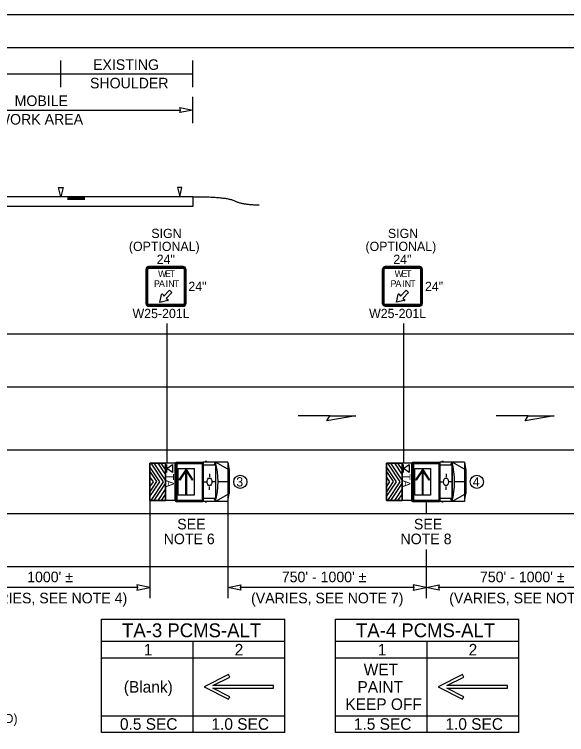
# Model space of a CAD drawing. Extents: x 0 to 17, y 0 to 11.
# Drawn here: x 8.5 to 12.68, y 5.55 to 11 of the extents above; entities that cross this region are included whole.
import ezdxf

# ---------------------------------------------------------------- set-up
doc = ezdxf.new("R2010")
doc.units = 0
for name, color, linetype in [('RD_ED_ShoulderPavedEdge', 7, 'Continuous'), ('RD_MK_LineEdgeWhite', 7, 'Continuous'), ('RD_MK_LineEdgeYellow', 7, 'Continuous'), ('RD_MK_LineLane', 7, 'Continuous'), ('SH_GI_PlotLimits', 7, 'Continuous'), ('SH_GI_SheetBorder3', 7, 'Continuous'), ('SH_TI_WZSectionCut', 7, 'Continuous'), ('TR_SN_ConstructionSigns', 7, 'Continuous'), ('TR_SN_SignNotes', 7, 'Continuous'), ('TR_WZ_PortableChangeMessageSign', 7, 'Continuous'), ('TR_WZ_PortableSignMountBlk-Org', 7, 'Continuous'), ('TR_WZ_TransportableAttenuator', 7, 'Continuous'), ('TR_WZ_WorkZoneDetails', 7, 'Continuous'), ('TR_WZ_WorkZoneTextCurrent', 7, 'Continuous')]:
    doc.layers.add(name, color=color, linetype=linetype)

msp = doc.modelspace()

# ---------------------------------------------------------------- linework, layer by layer
at = {"layer": 'RD_ED_ShoulderPavedEdge'}
for p, q in [((1.8283, 8.5807), (16.62, 8.5807)), ((1.8283, 6.8207), (16.62, 6.8207))]:
    msp.add_line(p, q, dxfattribs=at)
at = {"layer": 'RD_MK_LineEdgeWhite'}
msp.add_line((1.8283, 7.2207), (16.62, 7.2207), dxfattribs=at)
at = {"layer": 'RD_MK_LineEdgeYellow'}
msp.add_line((1.8283, 8.1807), (16.62, 8.1807), dxfattribs=at)
at = {"layer": 'RD_MK_LineLane'}
msp.add_line((16.62, 7.7007), (1.8283, 7.7007), dxfattribs=at)
at = {"layer": 'SH_GI_PlotLimits'}
msp.add_lwpolyline([(0, 11), (17, 11), (17, 0), (0, 0)], close=True, dxfattribs=at)
at = {"layer": 'SH_GI_SheetBorder3'}
msp.add_line((1, 10.75), (16.75, 10.75), dxfattribs=at)
at = {"layer": 'SH_TI_WZSectionCut'}
for p, q in [((8.8546, 10.45), (8.8546, 10.65)), ((9.8546, 10.45), (9.8546, 10.65)), ((7.6546, 10.55), (8.8546, 10.55)), ((8.8546, 10.55), (9.8546, 10.55)), ((9.8546, 10.176), (9.8546, 10.376)), ((7.6484, 10.276), (9.7609, 10.276)), ((9.8546, 9.6199), (5.4546, 9.6199)), ((9.0376, 9.6143), (8.9046, 9.6143)), ((9.0376, 9.6087), (8.9046, 9.6087)), ((9.0376, 9.603), (8.9046, 9.603)), ((9.0376, 9.5978), (8.9046, 9.5978)), ((9.8546, 9.6199), (9.8546, 9.5449)), ((9.8546, 9.5449), (5.4546, 9.5449))]:
    msp.add_line(p, q, dxfattribs=at)
for points in [[(9.8546, 10.276), (9.7564, 10.2567), (9.7609, 10.276), (9.7564, 10.2953)], [(8.838, 9.6897), (8.8713, 9.6897), (8.8547, 9.6199)]]:
    msp.add_lwpolyline(points, close=True, dxfattribs=at)
msp.add_lwpolyline([(9.7713, 9.6897), (9.7379, 9.6897), (9.7546, 9.6199), (9.7713, 9.6897)], dxfattribs=at)
msp.add_open_spline([(9.8546, 9.6199), (10.1058, 9.6201), (10.2313, 9.558), (10.3568, 9.5581)], degree=2, dxfattribs=at)
at = {"layer": 'TR_SN_ConstructionSigns'}
for p, q in [((9.5003, 9.0719), (9.5003, 8.8094)), ((9.5003, 8.8094), (9.5003, 9.0719)), ((9.5003, 9.0719), (9.5003, 8.8094)), ((9.505, 9.0719), (9.505, 8.8094)), ((9.5128, 8.8094), (9.5128, 9.0719)), ((9.7816, 9.0907), (9.5191, 9.0907)), ((9.5191, 9.0907), (9.7816, 9.0907)), ((9.7816, 9.0907), (9.5191, 9.0907)), ((9.7816, 9.086), (9.5191, 9.086)), ((9.5191, 9.0782), (9.7816, 9.0782)), ((9.7878, 9.0719), (9.7878, 8.8094)), ((9.7956, 8.8094), (9.7956, 9.0719)), ((9.8003, 8.8094), (9.8003, 9.0719)), ((9.8003, 9.0719), (9.8003, 8.8094)), ((9.8003, 8.8094), (9.8003, 9.0719)), ((11.2911, 9.072), (11.2911, 8.8095)), ((11.2911, 8.8095), (11.2911, 9.072)), ((11.2911, 9.072), (11.2911, 8.8095)), ((11.2958, 9.072), (11.2958, 8.8095)), ((11.3036, 8.8095), (11.3036, 9.072)), ((11.5723, 9.0907), (11.3098, 9.0907)), ((11.3098, 9.0907), (11.5723, 9.0907)), ((11.5723, 9.0907), (11.3098, 9.0907)), ((11.5723, 9.086), (11.3098, 9.086)), ((11.3098, 9.0782), (11.5723, 9.0782)), ((11.5786, 9.072), (11.5786, 8.8095)), ((11.5864, 8.8095), (11.5864, 9.072)), ((11.5911, 8.8095), (11.5911, 9.072)), ((11.5911, 9.072), (11.5911, 8.8095)), ((11.5911, 8.8095), (11.5911, 9.072)), ((9.6343, 8.8674), (9.6785, 8.9115)), ((9.6962, 8.8939), (9.652, 8.8497)), ((9.6785, 8.9115), (9.6962, 8.8939)), ((11.4251, 8.8674), (11.4693, 8.9116)), ((11.4869, 8.8939), (11.4427, 8.8497)), ((11.4693, 8.9116), (11.4869, 8.8939)), ((9.6045, 8.8198), (9.6176, 8.8796)), ((9.6261, 8.8808), (9.6343, 8.8674)), ((9.652, 8.8497), (9.6654, 8.8415)), ((11.3952, 8.8199), (11.4084, 8.8796)), ((11.4169, 8.8809), (11.4251, 8.8674)), ((11.4427, 8.8497), (11.4562, 8.8416)), ((9.7816, 8.8032), (9.5191, 8.8032)), ((9.5191, 8.7954), (9.7816, 8.7954)), ((9.5191, 8.7907), (9.7816, 8.7907)), ((9.7816, 8.7907), (9.5191, 8.7907)), ((9.5191, 8.7907), (9.7816, 8.7907)), ((9.6642, 8.833), (9.6045, 8.8198)), ((11.5723, 8.8032), (11.3098, 8.8032)), ((11.3098, 8.7954), (11.5723, 8.7954)), ((11.3098, 8.7907), (11.5723, 8.7907)), ((11.5723, 8.7907), (11.3098, 8.7907)), ((11.3098, 8.7907), (11.5723, 8.7907)), ((11.455, 8.833), (11.3952, 8.8199))]:
    msp.add_line(p, q, dxfattribs=at)
for centre, radius, start, end in [((9.5191, 9.0719), 0.0188, 90, 180), ((9.5191, 9.0719), 0.0188, 90, 180), ((9.5191, 9.0719), 0.0188, 90, 180), ((9.5191, 9.0719), 0.0141, 90, 180), ((9.5191, 9.0719), 0.00625, 90, 180), ((9.7816, 9.0719), 0.0188, 0, 90), ((9.7816, 9.0719), 0.0188, 0, 90), ((9.7816, 9.0719), 0.0188, 0, 90), ((9.7816, 9.0719), 0.0141, 0, 90), ((9.7816, 9.0719), 0.00625, 0, 90), ((11.3098, 9.072), 0.0188, 90, 180), ((11.3098, 9.072), 0.0188, 90, 180), ((11.3098, 9.072), 0.0188, 90, 180), ((11.3098, 9.072), 0.0141, 90, 180), ((11.3098, 9.072), 0.00625, 90, 180), ((11.5723, 9.072), 0.0188, 0, 90), ((11.5723, 9.072), 0.0188, 0, 90), ((11.5723, 9.072), 0.0188, 0, 90), ((11.5723, 9.072), 0.0141, 0, 90), ((11.5723, 9.072), 0.00625, 0, 90), ((9.6221, 8.8784), 0.00469, 31.1441, 165.4258), ((9.663, 8.8375), 0.00469, 284.5742, 58.8559), ((11.4129, 8.8784), 0.00469, 31.1441, 165.4258), ((11.4538, 8.8376), 0.00469, 284.5742, 58.8559), ((9.5191, 8.8094), 0.0188, 180, 270), ((9.5191, 8.8094), 0.0188, 180, 270), ((9.5191, 8.8094), 0.0188, 180, 270), ((9.5191, 8.8094), 0.0141, 180, 270), ((9.5191, 8.8094), 0.00625, 180, 270), ((9.7816, 8.8094), 0.0141, 270, 0), ((9.7816, 8.8094), 0.00625, 270, 0), ((9.7816, 8.8094), 0.0188, 270, 0), ((9.7816, 8.8094), 0.0188, 270, 0), ((9.7816, 8.8094), 0.0188, 270, 0), ((11.3098, 8.8095), 0.0188, 180, 270), ((11.3098, 8.8095), 0.0188, 180, 270), ((11.3098, 8.8095), 0.0188, 180, 270), ((11.3098, 8.8095), 0.0141, 180, 270), ((11.3098, 8.8095), 0.00625, 180, 270), ((11.5723, 8.8095), 0.0141, 270, 0), ((11.5723, 8.8095), 0.00625, 270, 0), ((11.5723, 8.8095), 0.0188, 270, 0), ((11.5723, 8.8095), 0.0188, 270, 0), ((11.5723, 8.8095), 0.0188, 270, 0)]:
    msp.add_arc(centre, radius, start, end, dxfattribs=at)
at = {"layer": 'TR_SN_SignNotes'}
for centre in [(9.98, 7.4607), (11.7708, 7.4607)]:
    msp.add_ellipse(centre, major_axis=(0, 0.0289), ratio=0.642144, dxfattribs=at)
at = {"layer": 'TR_WZ_PortableChangeMessageSign'}
for p, q in [((9.1639, 6.4207), (10.5499, 6.4207)), ((9.1639, 5.5639), (9.1639, 6.4207)), ((10.5499, 5.5639), (10.5499, 6.4207)), ((10.9348, 6.4207), (12.3208, 6.4207)), ((10.9348, 5.5639), (10.9348, 6.4207)), ((12.3208, 5.5639), (12.3208, 6.4207)), ((10.5499, 6.2527), (9.1639, 6.2527)), ((9.8569, 5.5639), (9.8569, 6.2527)), ((12.3208, 6.2527), (10.9348, 6.2527)), ((11.6278, 5.5639), (11.6278, 6.2527)), ((9.8569, 6.1267), (9.1639, 6.1267)), ((10.5499, 6.1267), (9.8569, 6.1267)), ((11.6278, 6.1267), (10.9348, 6.1267)), ((12.3208, 6.1267), (11.6278, 6.1267)), ((10.1249, 6.0017), (9.9409, 5.9083)), ((11.8958, 6.0017), (11.7118, 5.9083)), ((10.4659, 5.9188), (10.006, 5.9188)), ((10.006, 5.8978), (10.4659, 5.8978)), ((10.4659, 5.8978), (10.4659, 5.9188)), ((12.2368, 5.9188), (11.777, 5.9188)), ((11.777, 5.8978), (12.2368, 5.8978)), ((12.2368, 5.8978), (12.2368, 5.9188)), ((9.1639, 5.6899), (9.8569, 5.6899)), ((9.8569, 5.6899), (10.5499, 5.6899)), ((10.9348, 5.6899), (11.6278, 5.6899)), ((11.6278, 5.6899), (12.3208, 5.6899)), ((10.5499, 5.5639), (9.1639, 5.5639)), ((12.3208, 5.5639), (10.9348, 5.5639))]:
    msp.add_line(p, q, dxfattribs=at)
for points in [[(10.006, 5.9188), (10.1342, 5.9829), (10.1296, 5.9923), (10.1249, 6.0017)], [(11.777, 5.9188), (11.9052, 5.9829), (11.9005, 5.9923), (11.8958, 6.0017)], [(9.9409, 5.9083), (10.1249, 5.8149), (10.1296, 5.8243), (10.1342, 5.8337), (10.006, 5.8978)], [(11.7118, 5.9083), (11.8958, 5.8149), (11.9005, 5.8243), (11.9052, 5.8337), (11.777, 5.8978)]]:
    msp.add_lwpolyline(points, dxfattribs=at)
at = {"layer": 'TR_WZ_PortableSignMountBlk-Org'}
for p, q in [((9.6581, 7.5319), (9.6581, 7.5919)), ((11.4489, 7.5319), (11.4489, 7.5919))]:
    msp.add_line(p, q, dxfattribs=at)
for points in [[(9.6581, 7.5619), (9.7012, 7.5919), (9.7012, 7.5319)], [(11.4489, 7.5619), (11.492, 7.5919), (11.492, 7.5319)]]:
    msp.add_lwpolyline(points, close=True, dxfattribs=at)
at = {"layer": 'TR_WZ_TransportableAttenuator'}
for p, q in [((9.5368, 7.6018), (9.5623, 7.6018)), ((9.5368, 7.6018), (9.6303, 7.4609)), ((9.5623, 7.6018), (9.5368, 7.6018)), ((9.6469, 7.4734), (9.5623, 7.6018)), ((9.5899, 7.6018), (9.6153, 7.6018)), ((9.6153, 7.6018), (9.5899, 7.6018)), ((9.5899, 7.6018), (9.6469, 7.5149)), ((9.6469, 7.5541), (9.6153, 7.6018)), ((9.7274, 7.6018), (9.6469, 7.6018)), ((9.6469, 7.3202), (9.6469, 7.6018)), ((9.7179, 7.5966), (9.7179, 7.3248)), ((9.7223, 7.6057), (9.7267, 7.6057)), ((9.7267, 7.6057), (9.7267, 7.3156)), ((9.7274, 7.6106), (9.9305, 7.6106)), ((9.7274, 7.6106), (9.7274, 7.3107)), ((9.7274, 7.6013), (9.7274, 7.3202)), ((9.7332, 7.5987), (9.7332, 7.3227)), ((9.7332, 7.5987), (9.9248, 7.5987)), ((9.9248, 7.5987), (9.9248, 7.3227)), ((9.9305, 7.6106), (9.9305, 7.3107)), ((9.9333, 7.6106), (9.9333, 7.3107)), ((10.1197, 7.6106), (9.9333, 7.6106)), ((10.0248, 7.5874), (9.9333, 7.5874)), ((9.9599, 7.615), (9.9487, 7.615)), ((10.0248, 7.6106), (10.0129, 7.5874)), ((10.0248, 7.6106), (10.0248, 7.3107)), ((10.0265, 7.6106), (10.0265, 7.3107)), ((10.1197, 7.5557), (10.0265, 7.6106)), ((10.1197, 7.6106), (10.1197, 7.3107)), ((10.1197, 7.6106), (10.1289, 7.5501)), ((11.3276, 7.6018), (11.3531, 7.6018)), ((11.3276, 7.6018), (11.4211, 7.4609)), ((11.3531, 7.6018), (11.3276, 7.6018)), ((11.4377, 7.4734), (11.3531, 7.6018)), ((11.3807, 7.6018), (11.4061, 7.6018)), ((11.4061, 7.6018), (11.3807, 7.6018)), ((11.3807, 7.6018), (11.4377, 7.5149)), ((11.4377, 7.5541), (11.4061, 7.6018)), ((11.5182, 7.6018), (11.4377, 7.6018)), ((11.4377, 7.3202), (11.4377, 7.6018)), ((11.5087, 7.5966), (11.5087, 7.3248)), ((11.5131, 7.6057), (11.5175, 7.6057)), ((11.5175, 7.6057), (11.5175, 7.3156)), ((11.5182, 7.6106), (11.7213, 7.6106)), ((11.5182, 7.6106), (11.5182, 7.3107)), ((11.5182, 7.6013), (11.5182, 7.3202)), ((11.524, 7.5987), (11.524, 7.3227)), ((11.524, 7.5987), (11.7155, 7.5987)), ((11.7155, 7.5987), (11.7155, 7.3227)), ((11.7213, 7.6106), (11.7213, 7.3107)), ((11.724, 7.6106), (11.724, 7.3107)), ((11.9105, 7.6106), (11.724, 7.6106)), ((11.8156, 7.5874), (11.724, 7.5874)), ((11.7507, 7.615), (11.7395, 7.615)), ((11.8156, 7.6106), (11.8037, 7.5874)), ((11.8156, 7.6106), (11.8156, 7.3107)), ((11.8172, 7.6106), (11.8172, 7.3107)), ((11.9105, 7.5557), (11.8172, 7.6106)), ((11.9105, 7.6106), (11.9105, 7.3107)), ((11.9105, 7.6106), (11.9197, 7.5501)), ((9.529, 7.5385), (9.529, 7.575)), ((9.6042, 7.4618), (9.529, 7.575)), ((9.529, 7.575), (9.529, 7.5385)), ((9.529, 7.5385), (9.58, 7.4622)), ((9.6469, 7.5541), (9.6469, 7.5149)), ((9.6469, 7.5149), (9.6469, 7.5541)), ((10.1289, 7.5501), (10.1289, 7.3713)), ((11.3198, 7.5385), (11.3198, 7.575)), ((11.3949, 7.4618), (11.3198, 7.575)), ((11.3198, 7.575), (11.3198, 7.5385)), ((11.3198, 7.5385), (11.3708, 7.4622)), ((11.4377, 7.5541), (11.4377, 7.5149)), ((11.4377, 7.5149), (11.4377, 7.5541)), ((11.9197, 7.5501), (11.9197, 7.3713)), ((9.529, 7.4219), (9.529, 7.4999)), ((9.5551, 7.4611), (9.529, 7.4999)), ((9.529, 7.4999), (9.529, 7.4219)), ((9.6469, 7.4734), (9.6469, 7.4483)), ((9.6469, 7.4483), (9.6469, 7.4734)), ((9.7179, 7.4818), (9.7267, 7.4762)), ((9.9801, 7.5201), (9.98, 7.4959)), ((11.3198, 7.4219), (11.3198, 7.4999)), ((11.3459, 7.4611), (11.3198, 7.4999)), ((11.3198, 7.4999), (11.3198, 7.4219)), ((11.4377, 7.4734), (11.4377, 7.4483)), ((11.4377, 7.4483), (11.4377, 7.4734)), ((11.5087, 7.4818), (11.5175, 7.4762)), ((11.7708, 7.5201), (11.7708, 7.4959)), ((9.58, 7.4622), (9.529, 7.3854)), ((9.529, 7.3486), (9.6042, 7.4618)), ((9.529, 7.4219), (9.5551, 7.4611)), ((9.6303, 7.4609), (9.5367, 7.32)), ((9.5618, 7.32), (9.6469, 7.4483)), ((9.7179, 7.4395), (9.7267, 7.4452)), ((9.7203, 7.4607), (9.7243, 7.4607)), ((9.7223, 7.4649), (9.7223, 7.4564)), ((9.9403, 7.4609), (9.9569, 7.4608)), ((9.9615, 7.4601), (9.9615, 7.4601)), ((9.9801, 7.4012), (9.98, 7.4255)), ((10.0197, 7.4609), (10.0031, 7.4608)), ((10.1197, 7.4607), (10.0448, 7.4607)), ((11.3708, 7.4622), (11.3198, 7.3854)), ((11.3198, 7.3486), (11.3949, 7.4618)), ((11.3198, 7.4219), (11.3459, 7.4611)), ((11.4211, 7.4609), (11.3275, 7.32)), ((11.3526, 7.32), (11.4377, 7.4483)), ((11.5087, 7.4395), (11.5175, 7.4452)), ((11.511, 7.4607), (11.5151, 7.4607)), ((11.5131, 7.4649), (11.5131, 7.4564)), ((11.7311, 7.4609), (11.7477, 7.4608)), ((11.7523, 7.4601), (11.7523, 7.4601)), ((11.7708, 7.4012), (11.7708, 7.4255)), ((11.8105, 7.4609), (11.7939, 7.4608)), ((11.9105, 7.4607), (11.8356, 7.4607)), ((9.529, 7.3486), (9.529, 7.3854)), ((9.529, 7.3854), (9.529, 7.3486)), ((9.6469, 7.4068), (9.5893, 7.32)), ((9.6162, 7.32), (9.6469, 7.3654)), ((9.6469, 7.4068), (9.6469, 7.3654)), ((9.6469, 7.3654), (9.6469, 7.4068)), ((10.1197, 7.3656), (10.0265, 7.3107)), ((10.1197, 7.3107), (10.1289, 7.3713)), ((11.3198, 7.3486), (11.3198, 7.3854)), ((11.3198, 7.3854), (11.3198, 7.3486)), ((11.4377, 7.4068), (11.3801, 7.32)), ((11.407, 7.32), (11.4377, 7.3654)), ((11.4377, 7.4068), (11.4377, 7.3654)), ((11.4377, 7.3654), (11.4377, 7.4068)), ((11.9105, 7.3656), (11.8172, 7.3107)), ((11.9105, 7.3107), (11.9197, 7.3713)), ((9.5618, 7.32), (9.5367, 7.32)), ((9.5367, 7.32), (9.5618, 7.32)), ((9.6162, 7.32), (9.5893, 7.32)), ((9.5893, 7.32), (9.6162, 7.32)), ((9.7274, 7.3202), (9.6469, 7.3202)), ((9.7223, 7.3156), (9.7267, 7.3156)), ((9.7274, 7.3107), (9.9305, 7.3107)), ((9.7332, 7.3227), (9.9248, 7.3227)), ((10.0248, 7.3339), (9.9333, 7.3339)), ((10.1197, 7.3107), (9.9333, 7.3107)), ((10.015, 7.3339), (10.0248, 7.3107)), ((11.3526, 7.32), (11.3275, 7.32)), ((11.3275, 7.32), (11.3526, 7.32)), ((11.407, 7.32), (11.3801, 7.32)), ((11.3801, 7.32), (11.407, 7.32)), ((11.5182, 7.3202), (11.4377, 7.3202)), ((11.5131, 7.3156), (11.5175, 7.3156)), ((11.5182, 7.3107), (11.7213, 7.3107)), ((11.524, 7.3227), (11.7155, 7.3227)), ((11.8156, 7.3339), (11.724, 7.3339)), ((11.9105, 7.3107), (11.724, 7.3107)), ((11.8058, 7.3339), (11.8156, 7.3107)), ((9.9587, 7.3065), (9.9475, 7.3065)), ((11.7495, 7.3065), (11.7383, 7.3065))]:
    msp.add_line(p, q, dxfattribs=at)
for points in [[(9.6469, 7.32), (9.529, 7.32), (9.529, 7.6018), (9.6469, 7.6018)], [(11.4377, 7.32), (11.3198, 7.32), (11.3198, 7.6018), (11.4377, 7.6018)], [(9.7432, 7.5624), (9.8632, 7.5624), (9.8632, 7.3589), (9.7432, 7.3589)], [(9.7515, 7.4767), (9.8032, 7.5542), (9.8012, 7.544), (9.7548, 7.4745)], [(9.8032, 7.5542), (9.8052, 7.544), (9.8012, 7.544)], [(9.8012, 7.3671), (9.8012, 7.544), (9.8052, 7.544), (9.8052, 7.3671)], [(9.8032, 7.5542), (9.8548, 7.4767), (9.8515, 7.4745), (9.8052, 7.544)], [(11.534, 7.5624), (11.654, 7.5624), (11.654, 7.3589), (11.534, 7.3589)], [(11.5423, 7.4767), (11.594, 7.5542), (11.592, 7.544), (11.5456, 7.4745)], [(11.594, 7.5542), (11.596, 7.544), (11.592, 7.544)], [(11.592, 7.3671), (11.592, 7.544), (11.596, 7.544), (11.596, 7.3671)], [(11.594, 7.5542), (11.6456, 7.4767), (11.6423, 7.4745), (11.596, 7.544)]]:
    msp.add_lwpolyline(points, close=True, dxfattribs=at)
for points in [[(9.6469, 7.6018), (9.529, 7.6018), (9.529, 7.32), (9.6469, 7.3202)], [(11.4377, 7.6018), (11.3198, 7.6018), (11.3198, 7.32), (11.4377, 7.3202)]]:
    msp.add_lwpolyline(points, dxfattribs=at)
for centre, major_axis, start_param, end_param in [((9.7223, 7.5966), (0, 0.00915), 6.283185, 7.853982), ((9.8932, 7.4606), (0, 0.3148), 4.215852, 5.209111), ((11.5131, 7.5966), (0, 0.00915), 6.283185, 7.853982), ((11.684, 7.4606), (0, 0.3148), 4.215852, 5.209111), ((9.7223, 7.3248), (0, -0.00915), 4.712389, 6.283185), ((11.5131, 7.3248), (0, -0.00915), 4.712389, 6.283185)]:
    msp.add_ellipse(centre, major_axis=major_axis, ratio=0.481608, start_param=start_param, end_param=end_param, dxfattribs=at)
for centre, major_axis, ratio in [((9.98, 7.4607), (0, -0.0289), 0.642144), ((11.7708, 7.4607), (0, -0.0289), 0.642144), ((9.7223, 7.4607), (0, -0.00422), 0.481608), ((11.5131, 7.4607), (0, -0.00422), 0.481608)]:
    msp.add_ellipse(centre, major_axis=major_axis, ratio=ratio, dxfattribs=at)
at = {"layer": 'TR_WZ_WorkZoneDetails'}
for p, q in [((9.6568, 8.6607), (9.6568, 7.6018)), ((11.4476, 8.6607), (11.4476, 7.6018)), ((10.892, 7.96), (10.6509, 7.96)), ((12.392, 7.96), (12.1509, 7.96)), ((9.529, 7.33), (9.529, 6.5807)), ((10.1196, 7.3207), (10.1196, 6.5807)), ((11.6197, 7.3107), (11.6197, 7.2207)), ((11.6197, 6.9487), (11.6197, 6.5807)), ((9.4353, 6.6607), (8.1227, 6.6607)), ((11.526, 6.6607), (10.2133, 6.6607)), ((13.0259, 6.6607), (11.7135, 6.6607))]:
    msp.add_line(p, q, dxfattribs=at)
for points in [[(11.0885, 7.96), (10.8697, 7.9214), (10.892, 7.96)], [(12.5885, 7.96), (12.3697, 7.9214), (12.392, 7.96)], [(9.529, 6.6607), (9.4307, 6.68), (9.4353, 6.6607), (9.4307, 6.6415)], [(10.1196, 6.6607), (10.2179, 6.68), (10.2133, 6.6607), (10.2179, 6.6415)], [(11.6197, 6.6607), (11.5215, 6.68), (11.526, 6.6607), (11.5215, 6.6415)], [(11.6197, 6.6607), (11.718, 6.68), (11.7135, 6.6607), (11.718, 6.6415)]]:
    msp.add_lwpolyline(points, close=True, dxfattribs=at)
for centre in [(10.2135, 7.4607), (12.0044, 7.4607)]:
    msp.add_circle(centre, 0.05, dxfattribs=at)

# ---------------------------------------------------------------- texts
at = {"layer": 'SH_TI_WZSectionCut'}
for s, p in [('EXISTING', (9.0986, 10.58)), ('SHOULDER', (9.0757, 10.44))]:
    msp.add_text(s, height=0.08, rotation=360, dxfattribs=at).set_placement(p)
for s, p in [('MOBILE', (8.5051, 10.306)), ('WORK AREA', (8.3696, 10.166))]:
    msp.add_text(s, height=0.08, dxfattribs=at).set_placement(p)
at = {"layer": 'TR_SN_ConstructionSigns'}
for s, height, p in [('SIGN', 0.07, (9.54, 9.3067)), ('SIGN', 0.07, (11.3307, 9.3067)), ('(OPTIONAL)', 0.07, (9.3702, 9.2087)), ('(OPTIONAL)', 0.07, (11.161, 9.2087)), ('24"', 0.07, (9.5808, 9.1107)), ('24"', 0.07, (11.3716, 9.1107)), ('W', 0.05, (9.5913, 9.0115)), ('E', 0.05, (9.6433, 9.0115)), ('T', 0.05, (9.6783, 9.0115)), ('W', 0.05, (11.3821, 9.0116)), ('E', 0.05, (11.4341, 9.0116)), ('T', 0.05, (11.4691, 9.0116)), ('P', 0.05, (9.5606, 8.9365)), ('A', 0.05, (9.5976, 8.9365)), ('I', 0.05, (9.6476, 8.9365)), ('N', 0.05, (9.6676, 8.9365)), ('T', 0.05, (9.7091, 8.9365)), ('24"', 0.07, (9.8203, 8.9057)), ('P', 0.05, (11.3513, 8.9366)), ('A', 0.05, (11.3883, 8.9366)), ('I', 0.05, (11.4383, 8.9366)), ('N', 0.05, (11.4583, 8.9366)), ('T', 0.05, (11.4998, 8.9366)), ('24"', 0.07, (11.6111, 8.9057)), ('W25-201L', 0.07, (9.3975, 8.7007)), ('W25-201L', 0.07, (11.1882, 8.7007)), ('W20-5R (TRUCK/TA-MOUNTED)', 0.07, (7.1234, 5.6336))]:
    msp.add_text(s, height=height, dxfattribs=at).set_placement(p)
at = {"layer": 'TR_WZ_PortableChangeMessageSign'}
for s, height, p in [('TA-3 PCMS-ALT', 0.105, (9.3181, 6.2842)), ('TA-4 PCMS-ALT', 0.105, (11.0891, 6.2842)), ('1', 0.0875, (9.483, 6.146)), ('2', 0.0875, (10.1709, 6.146)), ('1', 0.0875, (11.2539, 6.146)), ('2', 0.0875, (11.9419, 6.146)), ('WET', 0.0875, (11.1476, 5.9958)), ('(Blank)', 0.0875, (9.3316, 5.8646)), ('PAINT', 0.0875, (11.1005, 5.8646)), ('KEEP OFF', 0.0875, (11.0087, 5.7333)), ('0.5 SEC', 0.0875, (9.3022, 5.5832)), ('1.0 SEC', 0.0875, (9.9952, 5.5832)), ('1.5 SEC', 0.0875, (11.0731, 5.5832)), ('1.0 SEC', 0.0875, (11.7661, 5.5832))]:
    msp.add_text(s, height=height, rotation=360, dxfattribs=at).set_placement(p)
at = {"layer": 'TR_WZ_TransportableAttenuator'}
for p in [(9.651, 7.5229), (11.4418, 7.5229)]:
    msp.add_text('TA', height=0.06, rotation=270, dxfattribs=at).set_placement(p)
at = {"layer": 'TR_WZ_WorkZoneDetails'}
for s, p in [('3', (10.1829, 7.4257)), ('4', (11.973, 7.4257))]:
    msp.add_text(s, height=0.07, dxfattribs=at).set_placement(p)
at = {"layer": 'TR_WZ_WorkZoneTextCurrent'}
for s, p in [('SEE', (9.7362, 7.1007)), ('SEE', (11.5277, 7.1007)), ('NOTE 6', (9.6334, 6.9887)), ('NOTE 8', (11.4261, 6.9887)), ("1000' ±", (8.5999, 6.7007)), ("750' - 1000' ±", (10.5275, 6.7007)), ("750' - 1000' ±", (12.0275, 6.7007)), ('(VARIES, SEE NOTE 4)', (8.2044, 6.5407)), ('(VARIES, SEE NOTE 7)', (10.295, 6.5407)), ('(VARIES, SEE NOTE 7)', (11.795, 6.5407))]:
    msp.add_text(s, height=0.08, dxfattribs=at).set_placement(p)

doc.saveas('drawing.dxf')
